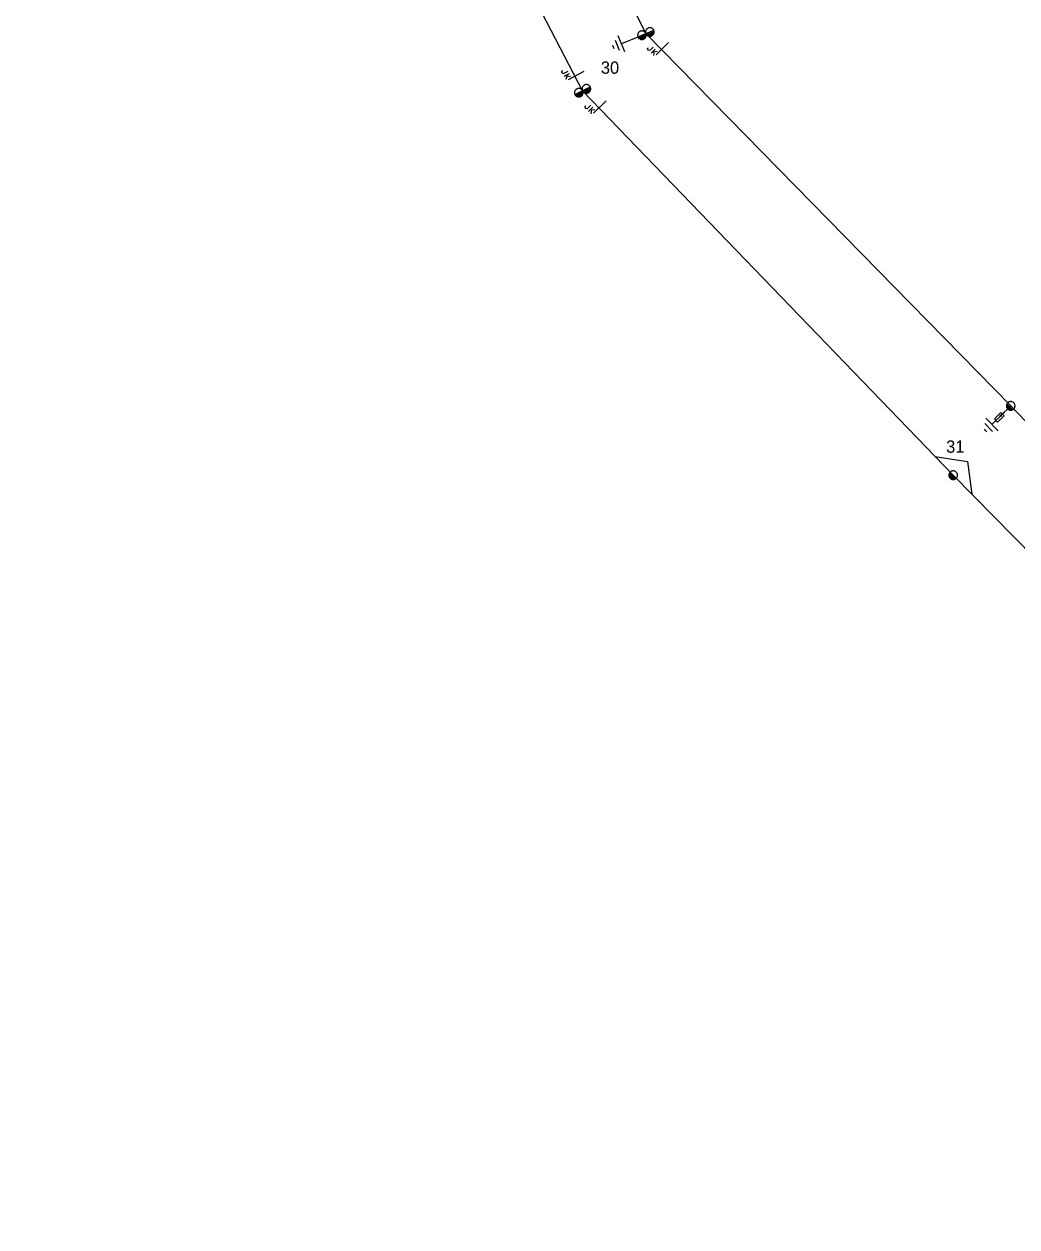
# Model space of a CAD drawing. Extents: x -540879 to -537255, y -1184046 to -1180016.
# Drawn here: x -539155.8 to -539014.6, y -1181553.6 to -1181382.6 of the extents above; entities that cross this region are included whole.
import ezdxf

# ---------------------------------------------------------------- set-up
doc = ezdxf.new("R2010")
doc.units = 0
for name, color, linetype in [('Vrstva 1', 7, 'Continuous'), ('Vrstva 13', 7, 'Continuous'), ('Vrstva 14', 7, 'Continuous'), ('Vrstva 15', 7, 'Continuous'), ('Vrstva 16', 7, 'Continuous'), ('Vrstva 18', 7, 'Continuous'), ('Vrstva 2', 7, 'Continuous')]:
    doc.layers.add(name, color=color, linetype=linetype)

# ---------------------------------------------------------------- blocks, each defined once
blk = doc.blocks.new('VN840')
at = {"layer": 'Vrstva 15'}
for points in [[(-0.01, 1.41), (-0.01, -1.09)], [(-1.51, -1.24), (-1.51, -1.15)], [(-1.48, -1.35), (-1.51, -1.24)], [(-1.33, -1.42), (-1.48, -1.35)], [(-1.27, -1.42), (-1.33, -1.42)], [(-1.13, -1.35), (-1.27, -1.42)], [(-1.09, -1.24), (-1.13, -1.35)], [(-1.09, -0.59), (-1.09, -1.24)], [(-0.68, -0.59), (-0.68, -1.42)], [(-0.68, -1.11), (-0.27, -0.59)], [(-0.54, -0.94), (-0.2, -1.42)]]:
    blk.add_lwpolyline(points, dxfattribs=at)
blk = doc.blocks.new('VN860')
at = {"layer": 'Vrstva 15'}
for points in [[(-3.74, 0), (0.01, 2.82)], [(0.01, 2.82), (3.76, 0)]]:
    blk.add_lwpolyline(points, dxfattribs=at)
blk = doc.blocks.new('VN440')
at = {"layer": 'Vrstva 2'}
for points in [[(1.22, 0), (1.21, 0.13), (1.19, 0.25), (1.16, 0.38), (1.11, 0.5), (1.05, 0.61), (0.98, 0.72), (0.9, 0.82), (0.81, 0.91), (0.71, 0.99), (0.6, 1.06), (0.49, 1.12), (0.37, 1.16), (0.25, 1.2), (0.12, 1.22), (-0.01, 1.22), (-0.14, 1.22), (-0.26, 1.2), (-0.39, 1.16), (-0.51, 1.12), (-0.62, 1.06), (-0.73, 0.99), (-0.83, 0.91), (-0.92, 0.82), (-1, 0.72), (-1.07, 0.61), (-1.13, 0.5), (-1.18, 0.38), (-1.21, 0.25), (-1.23, 0.13), (-1.24, 0), (-1.23, -0.13), (-1.21, -0.26), (-1.18, -0.38), (-1.13, -0.5), (-1.07, -0.62), (-1, -0.73), (-0.92, -0.83), (-0.83, -0.92), (-0.73, -1), (-0.62, -1.07), (-0.51, -1.13), (-0.39, -1.17), (-0.26, -1.2), (-0.14, -1.23), (-0.01, -1.23), (0.12, -1.23), (0.25, -1.2), (0.37, -1.17), (0.49, -1.13), (0.6, -1.07), (0.71, -1), (0.81, -0.92), (0.9, -0.83), (0.98, -0.73), (1.05, -0.62), (1.11, -0.5), (1.16, -0.38), (1.19, -0.26), (1.21, -0.13), (1.22, 0)], [(-1.24, 0), (1.22, 0)], [(-1.18, -0.34), (1.1, -0.34)], [(-1.01, -0.63), (0.97, -0.63)], [(-0.74, -0.92), (0.68, -0.92)]]:
    blk.add_lwpolyline(points, dxfattribs=at)
blk = doc.blocks.new('VN820')
at = {"layer": 'Vrstva 13'}
for points in [[(0, 0), (0, -2.1)], [(-0.32, -1.63), (0.34, -1.63)], [(-0.32, -2.95), (-0.32, -1.63)], [(0.34, -1.63), (0.34, -2.95)], [(0.34, -2.95), (-0.32, -2.95)], [(0, -2.1), (-0.12, -1.86)], [(0, -2.1), (0.12, -1.86)], [(0, -2.95), (0, -3.75)]]:
    blk.add_lwpolyline(points, dxfattribs=at)
blk = doc.blocks.new('VN810')
at = {"layer": 'Vrstva 14'}
for points in [[(0, -1.25), (0, -3.75)], [(1.25, -3.75), (-1.25, -3.75)], [(0.77, -4.37), (-0.8, -4.37)], [(0, -5), (-0.25, -5)], [(0.27, -5), (0, -5)]]:
    blk.add_lwpolyline(points, dxfattribs=at)
blk = doc.blocks.new('VN450')
at = {"layer": 'Vrstva 2'}
for points in [[(0, 0), (-0.01, 0.13), (-0.03, 0.25), (-0.06, 0.38), (-0.11, 0.5), (-0.16, 0.61), (-0.23, 0.72), (-0.31, 0.82), (-0.4, 0.91), (-0.5, 0.99), (-0.61, 1.06), (-0.72, 1.11), (-0.84, 1.16), (-0.97, 1.19), (-1.09, 1.21), (-1.22, 1.22), (-1.35, 1.21), (-1.47, 1.19), (-1.59, 1.16), (-1.71, 1.11), (-1.83, 1.06), (-1.93, 0.99), (-2.03, 0.91), (-2.12, 0.82), (-2.2, 0.72), (-2.27, 0.61), (-2.33, 0.5), (-2.38, 0.38), (-2.41, 0.25), (-2.43, 0.13), (-2.44, 0), (-2.43, -0.13), (-2.41, -0.25), (-2.38, -0.38), (-2.33, -0.5), (-2.27, -0.61), (-2.2, -0.72), (-2.12, -0.82), (-2.03, -0.91), (-1.93, -0.99), (-1.83, -1.06), (-1.71, -1.11), (-1.59, -1.16), (-1.47, -1.19), (-1.35, -1.21), (-1.22, -1.22), (-1.09, -1.21), (-0.97, -1.19), (-0.84, -1.16), (-0.72, -1.11), (-0.61, -1.06), (-0.5, -0.99), (-0.4, -0.91), (-0.31, -0.82), (-0.23, -0.72), (-0.16, -0.61), (-0.11, -0.5), (-0.06, -0.38), (-0.03, -0.25), (-0.01, -0.13), (0, 0)], [(-2.44, 0), (2.44, 0)], [(2.44, 0), (2.43, 0.13), (2.41, 0.25), (2.38, 0.38), (2.33, 0.5), (2.27, 0.61), (2.2, 0.72), (2.12, 0.82), (2.03, 0.91), (1.94, 0.99), (1.83, 1.06), (1.71, 1.11), (1.6, 1.16), (1.47, 1.19), (1.35, 1.21), (1.22, 1.22), (1.09, 1.21), (0.97, 1.19), (0.84, 1.16), (0.72, 1.11), (0.61, 1.06), (0.5, 0.99), (0.4, 0.91), (0.31, 0.82), (0.23, 0.72), (0.16, 0.61), (0.11, 0.5), (0.06, 0.38), (0.03, 0.25), (0.01, 0.13), (0, 0), (0.01, -0.13), (0.03, -0.25), (0.06, -0.38), (0.11, -0.5), (0.16, -0.61), (0.23, -0.72), (0.31, -0.82), (0.4, -0.91), (0.5, -0.99), (0.61, -1.06), (0.72, -1.11), (0.84, -1.16), (0.97, -1.19), (1.09, -1.21), (1.22, -1.22), (1.35, -1.21), (1.47, -1.19), (1.6, -1.16), (1.71, -1.11), (1.83, -1.06), (1.94, -0.99), (2.03, -0.91), (2.12, -0.82), (2.2, -0.72), (2.27, -0.61), (2.33, -0.5), (2.38, -0.38), (2.41, -0.25), (2.43, -0.13), (2.44, 0)], [(-2.4, -0.31), (-0.04, -0.31)], [(-2.26, -0.61), (-0.17, -0.61)], [(-2.01, -0.92), (-0.42, -0.92)], [(0.04, -0.31), (2.4, -0.31)], [(0.17, -0.61), (2.27, -0.61)], [(0.42, -0.92), (2.02, -0.92)]]:
    blk.add_lwpolyline(points, dxfattribs=at)

msp = doc.modelspace()

# ---------------------------------------------------------------- linework, layer by layer
at = {"layer": 'Vrstva 1'}
for points in [[(-539146.14, -1181230.44), (-539111.36, -1181296.54), (-539067.4, -1181383.96), (-539015.51, -1181436.9), (-538960.93, -1181493.88), (-538903.36, -1181553.62)], [(-538939.39, -1181533.04), (-538968.73, -1181502.62), (-539023.69, -1181446.75), (-539076.4, -1181392.09), (-539119.1, -1181309.84), (-539155.83, -1181236.81)]]:
    msp.add_lwpolyline(points, dxfattribs=at)

# ---------------------------------------------------------------- block references
at = {"layer": 'Vrstva 13'}
for name, p, xscale, yscale, rotation in [('VN450', (-539067.4, -1181383.96), 0.5, 0.5, 22.59604730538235), ('VN450', (-539076.4, -1181392.09), 0.5, 0.49999999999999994, 26.82880012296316), ('VN440', (-539015.51, -1181436.89), 0.49999999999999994, 0.5000000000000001, -45.57181110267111), ('VN440', (-539023.69, -1181446.75), 0.5000000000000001, 0.5, -46.04066398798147)]:
    msp.add_blockref(name, p, dxfattribs=dict(at, xscale=xscale, yscale=yscale, rotation=rotation))
at = {"layer": 'Vrstva 15'}
for p, rotation in [((-539067.4, -1181383.96), -67.15866664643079), ((-539015.51, -1181436.9), -45.57220309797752)]:
    msp.add_blockref('VN810', p, dxfattribs=dict(at, rotation=rotation))
at = {"layer": 'Vrstva 16', "rotation": -45.57220309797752}
msp.add_blockref('VN820', (-539015.51, -1181436.9), dxfattribs=at)
at = {"layer": 'Vrstva 18'}
for name, p, rotation in [('VN840', (-539065.16, -1181386.24), -45.572222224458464), ('VN840', (-539077.47, -1181390.03), -62.56480004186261), ('VN840', (-539074.06, -1181394.52), -46.040986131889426), ('VN860', (-539023.69, -1181446.75), -45.47100555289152)]:
    msp.add_blockref(name, p, dxfattribs=dict(at, rotation=rotation))

# ---------------------------------------------------------------- texts
at = {"layer": 'Vrstva 14'}
for s, p in [('30', (-539073.8, -1181389.67)), ('31', (-539024.7, -1181443.55))]:
    msp.add_text(s, height=1.75, dxfattribs=at).set_placement(p)

doc.saveas('drawing.dxf')
